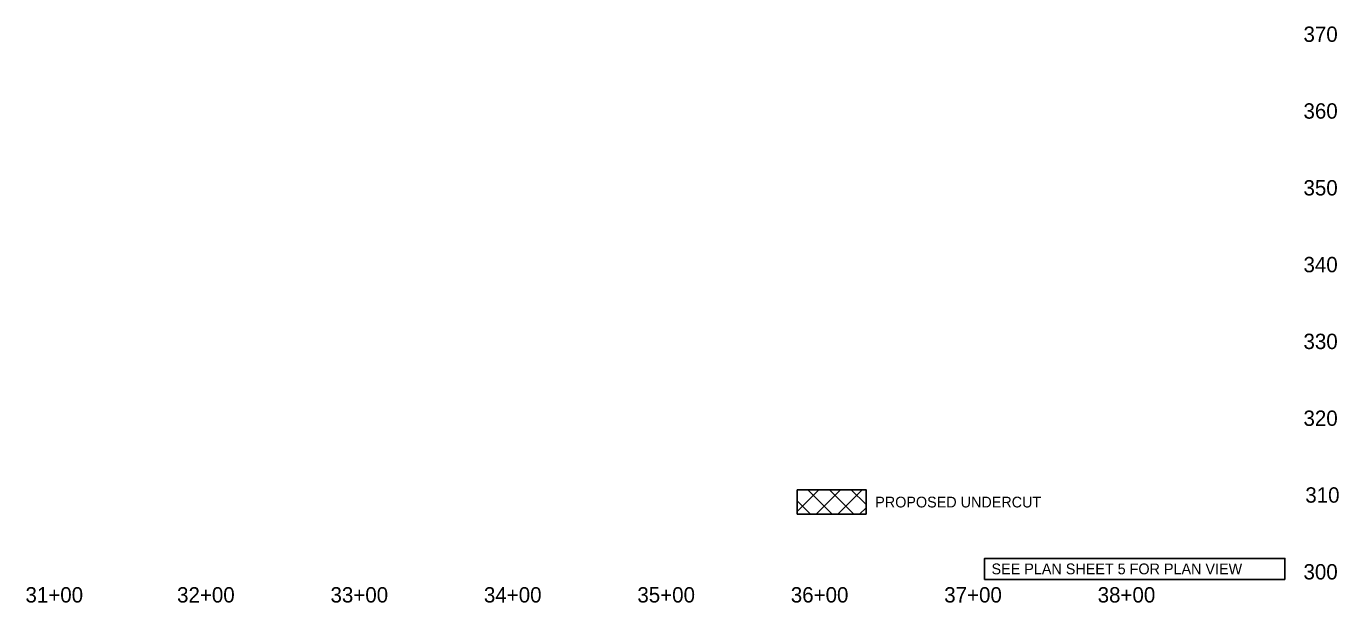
# Model space of a CAD drawing. Extents: x 2044664 to 2046614, y 755540 to 756566.
# Drawn here: x 2045631 to 2046487, y 755540 to 755916 of the extents above; entities that cross this region are included whole.
import ezdxf

# ---------------------------------------------------------------- set-up
doc = ezdxf.new("R2010")
doc.units = 0
for name, color, linetype in [('Default', 7, 'Continuous'), ('Exist Vertical Profile Horizontal Axis Label Major', 7, 'Continuous'), ('Exist Vertical Profile Vertical Axis Label', 7, 'Continuous'), ('Prop Grid Mask', 7, 'Continuous')]:
    doc.layers.add(name, color=color, linetype=linetype)

msp = doc.modelspace()

# ---------------------------------------------------------------- linework, layer by layer
at = {"layer": 'Default'}
for p, q in [((2046133.76, 755599.74), (2046147.8, 755613.78)), ((2046140.68, 755613.78), (2046156.45, 755598.02)), ((2046146.18, 755598.02), (2046161.95, 755613.78)), ((2046154.83, 755613.78), (2046170.59, 755598.02)), ((2046160.32, 755598.02), (2046176.09, 755613.78)), ((2046168.97, 755613.78), (2046178.59, 755604.16)), ((2046133.76, 755606.56), (2046142.31, 755598.02)), ((2046174.46, 755598.02), (2046178.59, 755602.14))]:
    msp.add_line(p, q, dxfattribs=at)
msp.add_lwpolyline([(2046133.76, 755613.78), (2046178.59, 755613.78), (2046178.59, 755598.02), (2046133.76, 755598.02)], close=True, dxfattribs=at)
at = {"layer": 'Prop Grid Mask'}
msp.add_lwpolyline([(2046451.63, 755555.41), (2046255.85, 755555.42), (2046255.85, 755569.07), (2046451.64, 755569.07)], close=True, dxfattribs=at)

# ---------------------------------------------------------------- texts
at = {"layer": 'Default'}
msp.add_text('PROPOSED UNDERCUT', height=7, dxfattribs=at).set_placement((2046184.61, 755602.29))
at = {"layer": 'Exist Vertical Profile Horizontal Axis Label Major'}
for s, p in [('31+00', (2045630.76, 755540.41)), ('32+00', (2045729.57, 755540.41)), ('33+00', (2045829.57, 755540.41)), ('34+00', (2045929.57, 755540.41)), ('35+00', (2046029.57, 755540.41)), ('36+00', (2046129.57, 755540.41)), ('37+00', (2046229.57, 755540.41)), ('38+00', (2046329.57, 755540.41))]:
    msp.add_text(s, height=10, dxfattribs=at).set_placement(p)
at = {"layer": 'Exist Vertical Profile Vertical Axis Label'}
for s, p in [('370', (2046463.72, 755905.41)), ('360', (2046463.72, 755855.41)), ('350', (2046463.72, 755805.41)), ('340', (2046463.72, 755755.41)), ('330', (2046463.72, 755705.41)), ('320', (2046463.72, 755655.41)), ('310', (2046464.92, 755605.41)), ('300', (2046463.72, 755555.41))]:
    msp.add_text(s, height=10, dxfattribs=at).set_placement(p)
at = {"layer": 'Prop Grid Mask'}
msp.add_text('SEE PLAN SHEET 5 FOR PLAN VIEW', height=7, rotation=359.9986, dxfattribs=at).set_placement((2046260.42, 755558.8))

doc.saveas('drawing.dxf')
